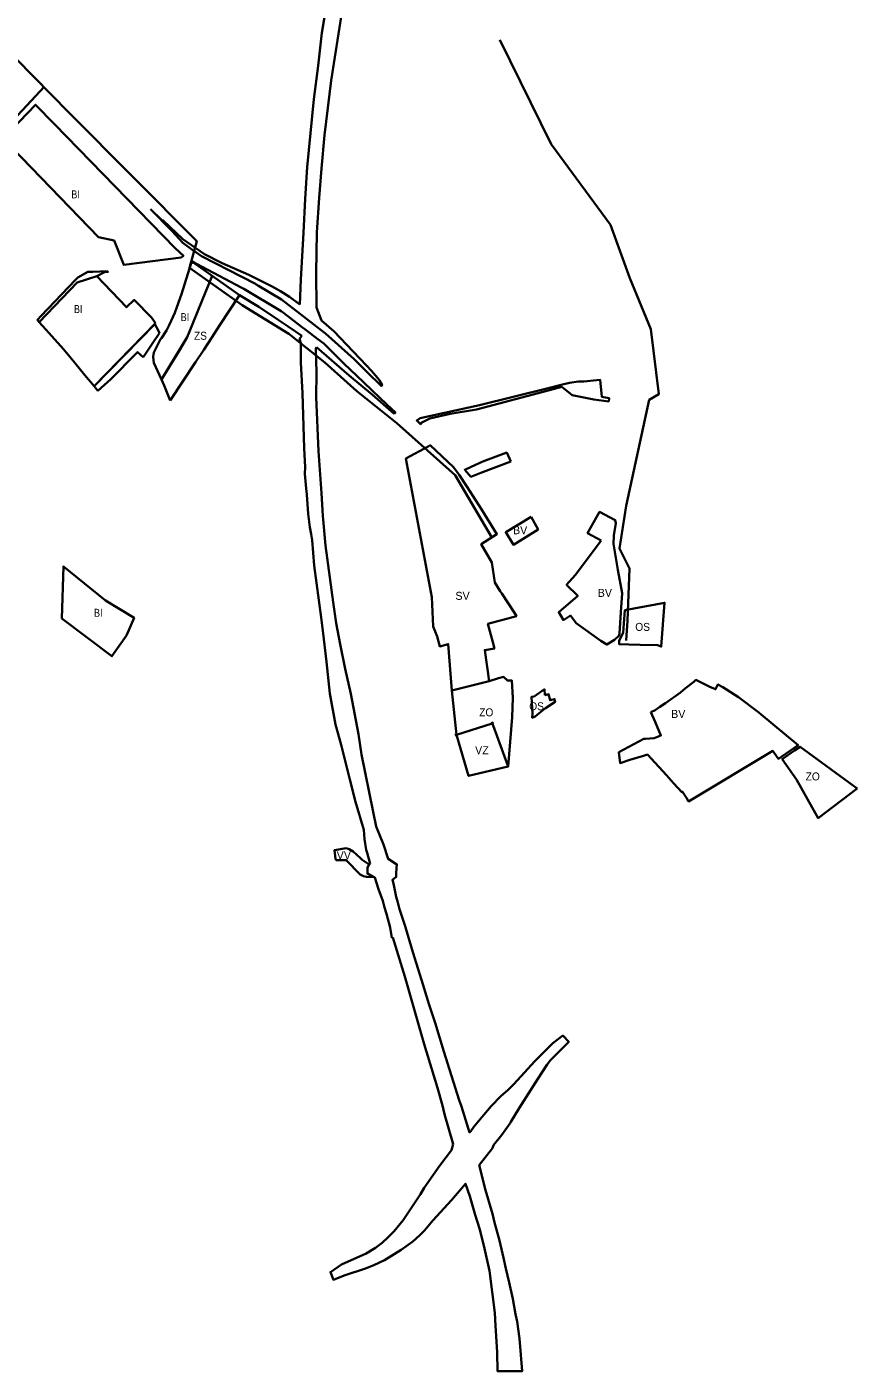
# Model space of a CAD drawing. Extents: x -650276 to -642489, y -1074311 to -1066720.
# Drawn here: x -645782 to -644537, y -1074038 to -1072023 of the extents above; entities that cross this region are included whole.
import ezdxf

# ---------------------------------------------------------------- set-up
doc = ezdxf.new("R2010")
doc.units = 0
doc.header["$LTSCALE"] = 4.8
doc.header["$PDMODE"] = 32
doc.header["$PDSIZE"] = 2.4
for name, color, linetype, lineweight in [('15', 7, 'Continuous', 35), ('18', 7, 'Continuous', 35), ('2', 7, 'Continuous', 35), ('24', 7, 'Continuous', 35), ('3', 7, 'Continuous', 35), ('36', 7, 'Continuous', 35), ('41', 7, 'Continuous', 35), ('42', 7, 'Continuous', 35), ('45', 7, 'Continuous', 35), ('54', 7, 'Continuous', 35), ('9', 7, 'Continuous', 35)]:
    doc.layers.add(name, color=color, linetype=linetype, lineweight=lineweight)
doc.layers.add('62', color=7, linetype='Continuous')

msp = doc.modelspace()

# ---------------------------------------------------------------- linework, layer by layer
at = {"layer": '15'}
for points in [[(-645763.06, -1072465.26), (-645706.039, -1072405.769), (-645676.53, -1072396.16)], [(-645661.3, -1072388.74), (-645682.59, -1072389.76), (-645690.37, -1072390.13), (-645705, -1072398.19), (-645708.94, -1072402.11)], [(-645676.53, -1072396.16), (-645676.53, -1072396.16), (-645665.32, -1072390.32), (-645660.16, -1072389.95), (-645661.3, -1072388.74)], [(-645708.94, -1072402.11), (-645760.02, -1072455.94), (-645765.95, -1072462.03), (-645763.06, -1072465.26)], [(-645582.84, -1072481.71), (-645584.46, -1072478.58), (-645589.862, -1072468.109), (-645680.87, -1072561.42), (-645675.13, -1072568.36)], [(-645607.07, -1072517.61), (-645605.95, -1072515.95), (-645604.82, -1072514.3), (-645592.9, -1072496.52), (-645583.13, -1072482.13), (-645582.84, -1072481.71)], [(-645675.13, -1072568.36), (-645655.65, -1072550.62), (-645617.87, -1072512.12), (-645615.95, -1072510.16), (-645607.07, -1072517.61)], [(-644926.81, -1072552.51), (-644946.57, -1072554.22), (-644954.57, -1072554.43), (-644967.97, -1072556.17), (-644978.56, -1072558.74), (-644999.72, -1072564.24), (-645102.73, -1072589.74), (-645192.06, -1072609.19), (-645197.044, -1072612.821), (-645190.71, -1072618.6)], [(-644919.75, -1072572.43), (-644921.84, -1072552.03), (-644926.81, -1072552.51)], [(-645147.13, -1072602.79), (-645107.58, -1072596.47), (-644997.92, -1072567.23), (-644979.55, -1072562.44), (-644963.97, -1072574.57)], [(-644963.97, -1072574.57), (-644931.48, -1072581.26), (-644909.02, -1072584.28)], [(-644909.02, -1072584.28), (-644908.59, -1072579.51), (-644919.23, -1072577.46), (-644919.75, -1072572.43)], [(-645190.71, -1072618.6), (-645190.59, -1072616.28), (-645179.6, -1072610.94), (-645177.56, -1072609.89), (-645147.13, -1072602.79)], [(-645056.08, -1072674.07), (-645062.131, -1072660.856), (-645098.016, -1072674.425), (-645115.56, -1072682.406), (-645124.933, -1072686.721), (-645116.11, -1072697.15)], [(-645116.11, -1072697.15), (-645100.9, -1072691.31), (-645056.08, -1072674.07)]]:
    msp.add_lwpolyline(points, dxfattribs=at)
at = {"layer": '18'}
msp.add_lwpolyline([(-645144.37, -1073017.64), (-645088.62, -1073003.45), (-645095.04, -1072957.07), (-645080.61, -1072954.43), (-645083.13, -1072944.94), (-645090.34, -1072917.86), (-645047.42, -1072906.05), (-645050.6, -1072901.03), (-645069.55, -1072872.12), (-645071.87, -1072868.45), (-645079.81, -1072855.89), (-645084.47, -1072825.67), (-645100.27, -1072798.46), (-645076.66, -1072783.06), (-645099.58, -1072746.945), (-645121.96, -1072711.68), (-645133.26, -1072694.17), (-645142.1, -1072682.57), (-645176.757, -1072649.968), (-645180.05, -1072651.77), (-645213.34, -1072669.98), (-645174.13, -1072877.93), (-645172.28, -1072921.42), (-645166.48, -1072936.5), (-645162.379, -1072951.55), (-645149.84, -1072948.13)], close=True, dxfattribs=at)
at = {"layer": '2'}
for points in [[(-645817.219, -1072189.975), (-645768.649, -1072139.283), (-645740.45, -1072168.23), (-645559.34, -1072354.42), (-645546.82, -1072365.72), (-645550.41, -1072368.47), (-645636.37, -1072379.57), (-645650.78, -1072342.73), (-645674, -1072338), (-645789.298, -1072218.833)], [(-645503.98, -1072395.64), (-645532.75, -1072375.41), (-645535.05, -1072376.72), (-645549.6, -1072423.39), (-645551.54, -1072428.66), (-645559.92, -1072451.41), (-645568.38, -1072469.68), (-645572.13, -1072477.78), (-645579.92, -1072489.22), (-645581.13, -1072491), (-645591.06, -1072511.06), (-645592.08, -1072517.43), (-645591.03, -1072526.14), (-645579.76, -1072551.45), (-645541.09, -1072487.98), (-645533.15, -1072468.21), (-645524.87, -1072447.61)], [(-645588.78, -1072467), (-645594.83, -1072458.48), (-645620.56, -1072432), (-645632.1, -1072442.93), (-645676.53, -1072396.16), (-645706.039, -1072405.769), (-645763.06, -1072465.26), (-645753.128, -1072476.383), (-645744.38, -1072486.18), (-645726.95, -1072505.7), (-645709.92, -1072526.3), (-645694.51, -1072544.93), (-645680.87, -1072561.42)], [(-645729.36, -1072909.65), (-645654.16, -1072966.3), (-645632.23, -1072935.28), (-645620.92, -1072908.65), (-645663.52, -1072882.58), (-645726.9, -1072831.5)]]:
    msp.add_lwpolyline(points, close=True, dxfattribs=at)
at = {"layer": '24'}
for points in [[(-645339.904, -1072462.677), (-645347.551, -1072443.527), (-645347.677, -1072391.355), (-645346.62, -1072330.914), (-645343.458, -1072278.998), (-645339.908, -1072235.158), (-645335.367, -1072185.207), (-645325.498, -1072102.789), (-645309.01, -1071998.147), (-645285.617, -1071875.733), (-645244.798, -1071696.585), (-645235.793, -1071663.703), (-645230.436, -1071634.261), (-645227.905, -1071625.277), (-645222.48, -1071606.08)], [(-645339.904, -1072462.677), (-645347.551, -1072443.527), (-645347.677, -1072391.355), (-645346.62, -1072330.914), (-645343.458, -1072278.998), (-645339.908, -1072235.158), (-645335.367, -1072185.207), (-645325.498, -1072102.789), (-645309.01, -1071998.147), (-645285.617, -1071875.733), (-645244.798, -1071696.585), (-645235.793, -1071663.703), (-645230.436, -1071634.261), (-645227.905, -1071625.277), (-645222.48, -1071606.08)], [(-645313.153, -1071883.081), (-645326.343, -1071952.807), (-645334.118, -1072001.954), (-645339.455, -1072031.565), (-645344.819, -1072081.225), (-645351.358, -1072130.815), (-645361.317, -1072232.824), (-645364.435, -1072280.268), (-645366.951, -1072331.609), (-645370.624, -1072401.447), (-645372.228, -1072438.764)], [(-645326.343, -1071952.807), (-645334.118, -1072001.954), (-645339.455, -1072031.565), (-645344.819, -1072081.225), (-645351.358, -1072130.815), (-645361.317, -1072232.824), (-645364.435, -1072280.268), (-645366.951, -1072331.609), (-645370.624, -1072401.447), (-645372.228, -1072438.764)], [(-645372.228, -1072438.764), (-645387.894, -1072427.453), (-645401.441, -1072419.033), (-645414.631, -1072411.611), (-645448.831, -1072394.325), (-645488.64, -1072376.782), (-645515.437, -1072363.447), (-645547.593, -1072340.827), (-645577.33, -1072312.704), (-645579.217, -1072312.425), (-645596.405, -1072296.114)], [(-645596.405, -1072296.114), (-645564.4, -1072328.61), (-645547.72, -1072346.19), (-645532.07, -1072358.01), (-645531.65, -1072358.29), (-645528.27, -1072360.53), (-645519.57, -1072366.3), (-645438.64, -1072408.1)], [(-645372.228, -1072438.764), (-645387.894, -1072427.453), (-645401.441, -1072419.033), (-645414.631, -1072411.611), (-645448.831, -1072394.325), (-645488.64, -1072376.782), (-645515.437, -1072363.447), (-645547.593, -1072340.827), (-645577.33, -1072312.704), (-645579.217, -1072312.425), (-645596.405, -1072296.114)], [(-645596.405, -1072296.114), (-645564.4, -1072328.61), (-645547.72, -1072346.19), (-645532.07, -1072358.01), (-645531.65, -1072358.29), (-645528.27, -1072360.53), (-645519.57, -1072366.3), (-645438.64, -1072408.1)], [(-645462.646, -1072425.015), (-645503.98, -1072395.64), (-645532.75, -1072375.41), (-645534.3, -1072374.33), (-645533.08, -1072373.71)], [(-645533.08, -1072373.71), (-645527.33, -1072377.73), (-645459.31, -1072413.95), (-645456.52, -1072415.6), (-645400.12, -1072449.03), (-645396.94, -1072451.44), (-645370.226, -1072471.736)], [(-645438.64, -1072408.1), (-645437.6, -1072408.64), (-645434.19, -1072410.67), (-645399.77, -1072431.12), (-645371.356, -1072453.119), (-645342.284, -1072475.625)], [(-645438.64, -1072408.1), (-645437.6, -1072408.64), (-645434.19, -1072410.67), (-645399.77, -1072431.12), (-645371.356, -1072453.119), (-645342.284, -1072475.625), (-645333.62, -1072482.33), (-645290.76, -1072520.92)], [(-645369.364, -1072485.931), (-645389.731, -1072471.612), (-645404.64, -1072461.72), (-645433.91, -1072442.56), (-645462.646, -1072425.015)], [(-645370.226, -1072471.736), (-645362.81, -1072477.37), (-645345.079, -1072490.836)], [(-645342.284, -1072475.625), (-645333.62, -1072482.33), (-645290.76, -1072520.92)], [(-645290.76, -1072520.92), (-645271.74, -1072539.96), (-645249.9, -1072561.25), (-645248.967, -1072559.511), (-645252.768, -1072552.178), (-645265.009, -1072538.358), (-645272.276, -1072530.154), (-645302.303, -1072499.014), (-645320.805, -1072479.495), (-645339.904, -1072462.677)], [(-645290.76, -1072520.92), (-645271.74, -1072539.96), (-645249.9, -1072561.25), (-645248.967, -1072559.511), (-645252.768, -1072552.178), (-645265.009, -1072538.358), (-645272.276, -1072530.154), (-645302.303, -1072499.014), (-645320.805, -1072479.495), (-645339.904, -1072462.677)], [(-645364.524, -1072682.575), (-645366.022, -1072654.462), (-645368.173, -1072571.881), (-645370.755, -1072525.734), (-645370.928, -1072496.619), (-645372.72, -1072490.314), (-645369.364, -1072485.931)], [(-645345.079, -1072490.836), (-645336.33, -1072497.48), (-645306.46, -1072527.08), (-645276.93, -1072555.11), (-645263.7, -1072567.8), (-645242, -1072588.6), (-645241.87, -1072588.722), (-645228.96, -1072600.865), (-645230.845, -1072602.888)], [(-645347.292, -1072502.877), (-645348.253, -1072505.583), (-645347.214, -1072540.97), (-645347.795, -1072577.893), (-645344.152, -1072658.857), (-645339.96, -1072721.587), (-645338.023, -1072755.969), (-645333.718, -1072799.987)], [(-645230.845, -1072602.888), (-645263.217, -1072574.314), (-645298.498, -1072545.352), (-645347.292, -1072502.877)], [(-645357.272, -1072772.771), (-645359.76, -1072752.865), (-645361.874, -1072723.527), (-645362.708, -1072714.781), (-645364.786, -1072692.977), (-645364.524, -1072682.575)], [(-645271.518, -1073261.16), (-645272.747, -1073256.762), (-645275.269, -1073240.71), (-645276.125, -1073226.571), (-645288.647, -1073184.518), (-645297.395, -1073151.294), (-645310.558, -1073098.946), (-645319.052, -1073068.6), (-645327.554, -1073022.214), (-645332.517, -1072974.538), (-645337.34, -1072932.073), (-645340.345, -1072908.029), (-645350.822, -1072830.388), (-645354.019, -1072792.454), (-645355.121, -1072782.993), (-645357.272, -1072772.771)], [(-645333.718, -1072799.987), (-645327.091, -1072848.387), (-645322.284, -1072885.085), (-645317.65, -1072916.642)], [(-645317.65, -1072916.642), (-645311.772, -1072947.945), (-645304.24, -1072985.372), (-645295.788, -1073022.556)], [(-645295.788, -1073022.556), (-645284.269, -1073083.286), (-645279.878, -1073113.356), (-645262.388, -1073199.409), (-645257.842, -1073221.36), (-645247.051, -1073248.736), (-645239.9, -1073270.025), (-645226.847, -1073278.345), (-645227.199, -1073283.366), (-645227.744, -1073292.736)], [(-645267.011, -1073277.282), (-645267.525, -1073275.443), (-645271.518, -1073261.16)], [(-645142.207, -1073697.878), (-645155.4, -1073652.618), (-645158.271, -1073639.962), (-645165.879, -1073613.368), (-645185.838, -1073547.75), (-645215.066, -1073446.251), (-645215.066, -1073446.251), (-645232.869, -1073388.079), (-645234.15, -1073388.3), (-645236.73, -1073372.92), (-645242.255, -1073352.652), (-645245.55, -1073343.196), (-645247.997, -1073332.992), (-645254.252, -1073315.648), (-645259.671, -1073298.157), (-645270.862, -1073292.263), (-645270.674, -1073289.436), (-645270.979, -1073285.096), (-645270.826, -1073282.937), (-645268.281, -1073278.357), (-645267.011, -1073277.282)], [(-645227.744, -1073292.736), (-645227.709, -1073297.105), (-645233.538, -1073301.748), (-645231.976, -1073307.175), (-645227.811, -1073326.92), (-645225.208, -1073335.374), (-645222.766, -1073345.378), (-645214.368, -1073370.824), (-645202.792, -1073410.042), (-645189.911, -1073451.528), (-645178.332, -1073489.109), (-645169.356, -1073515.725), (-645162.838, -1073537.623), (-645156.149, -1073559.097), (-645144.741, -1073595.63), (-645133.507, -1073631.745), (-645129.827, -1073641.333), (-645117.687, -1073680.357), (-645117.686, -1073680.357)], [(-645117.686, -1073680.357), (-645116.017, -1073678.548), (-645111.49, -1073672.015), (-645101.847, -1073660.215), (-645085.173, -1073640.634), (-645070.739, -1073625.929), (-645060.009, -1073616.53), (-645051.513, -1073608.124), (-645035.303, -1073590.199), (-645020.11, -1073573.585), (-644993.044, -1073546.324), (-644977.924, -1073535.072), (-644969.117, -1073544.254), (-644985.66, -1073560.69), (-644996.41, -1073571.97), (-645001.267, -1073578.582), (-645015.55, -1073599.96), (-645043.35, -1073644.04), (-645056.06, -1073664.2), (-645057, -1073666.46), (-645069.61, -1073683.97), (-645081.938, -1073699.551), (-645083.563, -1073703.795), (-645103.289, -1073729.161), (-645093.67, -1073766.618), (-645083.269, -1073802.165), (-645080.452, -1073815.426), (-645073.102, -1073842.105), (-645066.706, -1073868.355), (-645063.463, -1073884.343), (-645058.158, -1073905.265), (-645052.963, -1073929.814), (-645048.956, -1073952.909), (-645046.468, -1073963.613), (-645042.672, -1073989.007), (-645038.69, -1074038.132), (-645076.083, -1074038.132), (-645076.255, -1074009.906), (-645079.095, -1073970.117), (-645080.138, -1073950.909), (-645087.79, -1073887.702), (-645096.294, -1073849.905), (-645102.899, -1073824.258), (-645109.53, -1073803.725), (-645117.19, -1073775.726), (-645123.821, -1073757.192), (-645145.019, -1073782.052), (-645172.904, -1073812.299), (-645185.384, -1073827.415), (-645192.343, -1073834.369), (-645202.696, -1073843.79), (-645220.306, -1073856.451), (-645245.195, -1073871.581), (-645261.267, -1073879.292), (-645273.767, -1073884.401), (-645306.028, -1073894.816), (-645322.029, -1073901.212), (-645326.551, -1073889.691), (-645309.698, -1073878.501), (-645272.802, -1073861.555), (-645258.877, -1073853.094), (-645249.094, -1073845.668), (-645239.684, -1073837.487), (-645230.89, -1073828.274), (-645217.603, -1073811.984), (-645191.236, -1073772.952), (-645185.754, -1073763.32), (-645162.187, -1073729.808), (-645144.959, -1073707.044), (-645142.207, -1073697.878)]]:
    msp.add_lwpolyline(points, dxfattribs=at)
at = {"layer": '3'}
for points in [[(-645025.61, -1072757.17), (-645063.6, -1072780.26), (-645051.94, -1072799.21), (-645015.02, -1072776.01)], [(-644845.72, -1073050.14), (-644839.57, -1073064.5), (-644830.81, -1073084.98), (-644840.89, -1073089.3), (-644853.8, -1073089.99), (-644856.4, -1073090.13), (-644894.15, -1073110.3), (-644892.14, -1073126.36), (-644877.32, -1073121.83), (-644856.97, -1073115.6), (-644851, -1073113.77), (-644822.62, -1073144.71), (-644811.96, -1073156.75), (-644799.26, -1073170.13), (-644798.38, -1073169.56), (-644792.59, -1073178.73), (-644789.31, -1073183.93), (-644663.17, -1073108.27), (-644656.56, -1073117.4), (-644654.61, -1073120.1), (-644649.7, -1073116.65), (-644625.26, -1073099.51), (-644680.69, -1073053.67), (-644684.09, -1073050.8), (-644714.42, -1073027.62), (-644714.42, -1073027.62), (-644737.88, -1073012.62), (-644745.73, -1073008.64), (-644748.95, -1073015.64), (-644757.73, -1073012.05), (-644764.69, -1073008.87), (-644778.38, -1073001.84), (-644781.52, -1073004.39), (-644793.743, -1073014.293), (-644801.54, -1073020.61), (-644824.08, -1073036.56), (-644832.7, -1073042.34), (-644839.47, -1073046.89)]]:
    msp.add_lwpolyline(points, close=True, dxfattribs=at)
for points in [[(-644902.18, -1072797.88), (-644901.35, -1072785.36), (-644898.29, -1072766.55), (-644899.2, -1072762.14), (-644922.88, -1072749.97), (-644940.8, -1072781.48), (-644920.46, -1072792.92)], [(-644920.46, -1072792.92), (-644945.2, -1072826.3), (-644959.24, -1072844.92), (-644972.28, -1072859.02), (-644955.49, -1072875.78), (-644983.93, -1072900.24), (-644977.16, -1072912.11), (-644966.57, -1072905.23), (-644957.79, -1072916.73), (-644921.18, -1072943.17), (-644911.87, -1072948.76), (-644900.2, -1072941.67), (-644893.77, -1072935.88), (-644892.86, -1072932.6), (-644891.2, -1072900.09), (-644889.11, -1072871.66), (-644895.32, -1072836.6), (-644902.18, -1072797.88)]]:
    msp.add_lwpolyline(points, dxfattribs=at)
at = {"layer": '36'}
msp.add_lwpolyline([(-645137.5, -1073083.97), (-645119.34, -1073145.61), (-645060.1, -1073131.68), (-645082.6, -1073069.93), (-645083.681, -1073066.962)], dxfattribs=at)
for p in [(-645137.5, -1073083.97), (-645083.681, -1073066.962)]:
    msp.add_point(p, dxfattribs=at)
at = {"layer": '41'}
msp.add_line((-645566.54, -1072582.88), (-645528.81, -1072525.54), dxfattribs=at)
msp.add_lwpolyline([(-645528.81, -1072525.54), (-645516.37, -1072506.64), (-645504.48, -1072488.58), (-645492.61, -1072470.54), (-645462.65, -1072425.01), (-645503.98, -1072395.64), (-645524.87, -1072447.61), (-645533.15, -1072468.21), (-645541.09, -1072487.98), (-645553.35, -1072508.1), (-645579.76, -1072551.45), (-645575.9, -1072560.13), (-645566.54, -1072582.88)], dxfattribs=at)
at = {"layer": '42'}
for points in [[(-645054.12, -1073057.62), (-645052.94, -1073028.58), (-645054.44, -1073002.54), (-645060.95, -1073002.68), (-645066.66, -1072997.3), (-645074.333, -1072999.365), (-645088.62, -1073003.45), (-645144.37, -1073017.64), (-645137.5, -1073083.97), (-645083.681, -1073066.962), (-645082.6, -1073069.93), (-645060.1, -1073131.68)], [(-644536.62, -1073164.33), (-644536.62, -1073164.33), (-644622.03, -1073101.88), (-644622.03, -1073101.88), (-644630.58, -1073107.78), (-644648.95, -1073120.47), (-644627.53, -1073151.26), (-644604.13, -1073193), (-644595.18, -1073208.98)]]:
    msp.add_lwpolyline(points, close=True, dxfattribs=at)
at = {"layer": '45'}
msp.add_lwpolyline([(-645302.963, -1073253.878), (-645320.244, -1073256.876), (-645319.033, -1073270.116), (-645317.78, -1073272.18), (-645302.79, -1073271.837), (-645281.699, -1073293.356), (-645276.937, -1073295.951), (-645272.328, -1073296.82), (-645261.273, -1073297.322), (-645270.862, -1073292.263), (-645270.674, -1073289.436), (-645270.979, -1073285.096), (-645270.826, -1073282.937), (-645268.281, -1073278.357), (-645278.9, -1073271.29), (-645281.099, -1073269.264), (-645292.424, -1073258.825), (-645298.27, -1073255.65)], close=True, dxfattribs=at)
at = {"layer": '54'}
msp.add_line((-645885.363, -1072251.506), (-645755.385, -1072111.972), dxfattribs=at)
for points in [[(-646336.784, -1071524.232), (-646218.737, -1071612.767), (-646164.374, -1071674.897), (-645904.456, -1071961.331), (-645718.199, -1072151.712), (-645526.944, -1072343.922), (-645538, -1072384), (-645459, -1072440), (-645389, -1072483), (-645335, -1072526), (-645287, -1072569), (-645227, -1072617), (-645139.573, -1072694.628), (-645084.365, -1072788.086)], [(-645072.161, -1072041.834), (-644995.618, -1072198.247), (-644906.317, -1072319.547), (-644877.614, -1072399.349), (-644845.721, -1072475.959), (-644833.873, -1072573.126), (-644848.261, -1072581.918), (-644882.834, -1072740.552), (-644893.098, -1072804.559), (-644878.097, -1072834.588), (-644880.803, -1072913.277), (-644882.834, -1072942.847)]]:
    msp.add_lwpolyline(points, dxfattribs=at)
at = {"layer": '9'}
for points in [[(-644884.712, -1072897.147), (-644886.418, -1072916.953), (-644887.44, -1072930.94), (-644893.37, -1072942.61), (-644893.59, -1072947.97), (-644878.86, -1072948.42), (-644861.93, -1072948.94), (-644835.99, -1072949.74), (-644830.25, -1072951.9), (-644825.25, -1072885.96)], [(-645004.82, -1073024.63), (-645005.31, -1073015.68), (-645021.1, -1073026.69), (-645024.71, -1073026.95), (-645023.6, -1073052.12), (-645023.88, -1073058.37), (-645019.57, -1073056.46), (-645007.99, -1073047.31), (-645003.78, -1073043.96), (-644989.34, -1073034.58), (-644990.25, -1073030.54), (-644997.09, -1073032.21), (-644999.23, -1073023.29)]]:
    msp.add_lwpolyline(points, close=True, dxfattribs=at)

# ---------------------------------------------------------------- texts
at = {"layer": '62'}
for s, width, p in [('BI', 0.85, (-645715.06, -1072279.771)), ('BI', 0.85, (-645711.104, -1072451.727)), ('BI', 0.85, (-645551.06, -1072463.771)), ('ZS', 0.95, (-645531.06, -1072491.771)), ('BI', 0.85, (-645681, -1072907.167)), ('OS', 0.95, (-644869.265, -1072928.272)), ('OS', 0.95, (-645028.265, -1073047.272)), ('ZO', 0.95, (-645103.327, -1073056.309)), ('ZO', 0.95, (-644613.746, -1073152.429))]:
    msp.add_text(s, height=12, dxfattribs=dict(at, width=width)).set_placement(p)
for s, p in [('BV', (-645052.614, -1072783.26)), ('SV', (-645139.013, -1072881.667)), ('BV', (-644925.614, -1072877.26)), ('BV', (-644815.563, -1073058.759)), ('VZ', (-645109.496, -1073113.102)), ('VV', (-645317.075, -1073270.614))]:
    msp.add_text(s, height=12, dxfattribs=at).set_placement(p)

doc.saveas('drawing.dxf')
